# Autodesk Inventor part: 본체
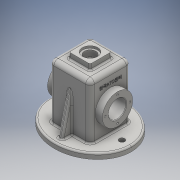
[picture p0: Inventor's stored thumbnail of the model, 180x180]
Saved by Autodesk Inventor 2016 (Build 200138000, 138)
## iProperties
Created: 2017-07
Part Number: 본체
Material: 일반
Document SubType Name: Modeling
Designer: USER
Density: 1 g/cm^3
Appearance: 기본값
Author: USER
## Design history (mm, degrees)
sketch "스케치1" dims "d14" = 75, "d15" = 65
  geometry: L1 (0, -65)-(0, 134.896); L2 (-82.834, 0)-(117.062, 0); L3 (-75, 53.384)-(-75, -73.215); L4 (75, 105.175)-(75, -110.044); 2 further points; 1 other entity
  constraints: 8 end point, 4 vertical, 4 vertical alignment, 2 horizontal alignment, 1 coincident, 1 horizontal, 1 perpendicular, 2 other
  dimensions: "d13" = 150 distance between parallel lines of L4 L3
extrude "돌출1" new body sketch "스케치1" distance "d16" = 10; taper "d17" = 0 deg
sketch "스케치2"
  geometry: L1 (-37, 110)-(37, 110); L2 (37, 110)-(37, 10); L3 (37, 10)-(-37, 10); L4 (-37, 10)-(-37, 110); L5 (65, 10)-(-65, 10) reference; L6 (-65, 0)-(65, 0) reference; 2 further points
  constraints: 8 end point, 2 parallel, 1 horizontal, 1 horizontal alignment, 1 midpoint, 1 perpendicular, 1 vertical alignment
  dimensions: "d18" = 74 distance between parallel lines of L2 L4; "d19" = 110 distance between parallel lines of L1 L6
extrude "돌출2" join sketch "스케치2" stored distance "d20" = 74; taper "d21" = 0 deg
sketch "스케치3"
  geometry: L1 (-37, 110)-(37, 110) reference; L2 (37, 110)-(37, 10) reference; L3 (-37, 10)-(37, 10) reference; L4 (-37, 10)-(-37, 110) reference; L5 (32, 105)-(-32, 105); L6 (-32, 105)-(-32, 15); L7 (-32, 15)-(32, 15); L8 (32, 15)-(32, 105); 1 further point
  constraints: 8 end point, 3 other
  dimensions: "d22" = 5 distance between parallel lines of L1 L5
extrude "돌출3" cut sketch "스케치3" stored distance "d23" = 64; taper "d24" = 0 deg
sketch "스케치4"
  geometry: L1 (-32, -32)-(32, -32); L2 (32, -32)-(32, 32); L3 (32, 32)-(-32, 32); L4 (-32, 32)-(-32, -32); 3 further points
  constraints: 8 end point, 2 midpoint, 2 parallel, 1 horizontal, 1 horizontal alignment, 1 perpendicular, 1 vertical alignment
  dimensions: "d25" = 64 distance of L3.end L1.start; "d26" = 64 distance of L2.end L3.end
extrude "돌출4" cut sketch "스케치4" stored distance "d27" = 69; taper "d28" = 0 deg
sketch "스케치5"
  geometry: 1 further point
sketch "스케치6"
  geometry: 1 further point
node "작업 평면1"
fillet "모깎기1" dims "d40" = 8
fillet "모깎기2" dims "d41" = 8
fillet "모깎기3" dims "d42" = 3
sketch "스케치15"
  geometry: L1 (0, 65)-(0, -65) reference; C1 r 27.5 at (55, 0); 2 further points
  constraints: 1 centre point, 1 horizontal alignment, 1 midpoint
  dimensions: "d56" = 55 diameter of C1; "d57" = 55 distance from line of L1 C1.centre
extrude "돌출7" join sketch "스케치15" distance "d58" = 13; taper "d59" = 0 deg
node "작업 평면2"
sketch "스케치16"
  geometry: C1 r 27.5 at (0, 0) reference; C2 r 16 at (0, 0); 1 further point
  constraints: 1 centre point, 1 coincident
  dimensions: "d60" = 32 diameter of C2
  node "투영된 루프3"
sketch "스케치17" dims "d63" = 45
  geometry: C1 r 27.5 at (0, 0) reference; 3 further points
  constraints: 2 horizontal alignment, 1 coincident, 2 other
hole "구멍2" sketch "스케치17" at (22.5, 0) diameter "d64" = 3.242; stored, may be unused: countersink angle "d68" = 90 deg, drill point angle "d70" = 118 deg; dims "d65" = 8, "d66" = 4, "d67" = 2, "d69" = 10
sketch "스케치18"
  geometry: L1 (65, 10)-(-65, 10) reference; L2 (-65, 0)-(65, 0) reference; L3 (65, 0)-(65, 10); L4 (55, 10)-(37, 82.194); L5 (37, 10)-(37, 102) reference; L6 (55, 10)-(37, 10); L7 (37, 82.194)-(37, 10); L8 (-37, 102)-(-37, 10) reference; L9 (-65, 10)-(-65, 0); L10 (-37, 82.194)-(-55, 10); L11 (-37, 82.194)-(-37, 10); L12 (65, 10)-(-65, 10) reference; L13 (-55, 10)-(-37, 10); 1 further point
  constraints: 16 end point, 4 point on line, 2 collinear, 2 perpendicular, 2 vertical
  dimensions: "d74" = 10 distance from line of L3 L4.start; "d75" = 14 deg angle of L4 L3; "d78" = 14 deg angle of L10 L9; "d79" = 10 distance from line of L9 L10.end
extrude "돌출9" join sketch "스케치18" stored distance "d80" = 8; taper "d81" = 0 deg
fillet "모깎기4" dims "d82" = 3
fillet "모깎기5" dims "d83" = 3
sketch "스케치19"
  geometry: L1 (86.305, 55)-(-68.103, 55); L2 (-29, 0)-(29, 0) reference; L3 (32, 102)-(32, 0) reference; L4 (32, 55)-(32, 82.5); L5 (32, 82.5)-(25, 75.5); L6 (25, 75.5)-(25, 55); 1 further point
  constraints: 8 end point, 4 point on line, 1 horizontal, 1 perpendicular
  dimensions: "d84" = 55 distance between parallel lines of L1 L2; "d85" = 7 distance between parallel lines of L3 L6; "d86" = 55 diameter of L4.end L1; "d87" = 135 deg angle of L3 L5
revolve "회전2" sketch "스케치19" stored, may be unused: angle "d88" = 90 deg
extrude "돌출10" cut sketch "스케치16" stored distance "d89" = 8; taper "d90" = 0 deg
sketch "스케치20"
  geometry: L1 (9, 9)-(49, 9); L2 (49, 9)-(49, 49); L3 (49, 49)-(9, 49); L4 (9, 49)-(9, 9); 3 further points
  constraints: 8 end point, 2 midpoint, 2 parallel, 1 horizontal, 1 horizontal alignment, 1 perpendicular, 1 vertical alignment
  dimensions: "d122" = 40 distance of L3.end L1.start; "d123" = 40 distance of L2.end L3.end
fillet "모깎기7" dims "d104" = 3
fillet "모깎기8" dims "d105" = 3
sketch "스케치23"
  geometry: L1 (-58, 0)-(58, 0); C1 r 5 at (-58, 0); C2 r 5 at (58, 0); 2 further points
  constraints: 2 centre point, 2 end point, 2 horizontal alignment, 1 coincident, 1 horizontal, 1 midpoint
  dimensions: "d106" = 10 diameter of C1; "d107" = 10 diameter of C2; "d109" = 58 distance of L1.start point (0, 0)
extrude "돌출14" cut sketch "스케치23" stored distance "d110" = 4; taper "d111" = 0 deg
chamfer "모따기1" distance "d112" = 1; stored, may be unused: second distance "d113" = 2, angle "d114" = 45 deg
extrude "돌출15" join sketch "스케치20" distance "d124" = 10; taper "d125" = -5 deg
sketch "스케치27"
  geometry: C1 r 14 at (29, 29); 1 further point
  constraints: 1 centre point, 1 coincident
  dimensions: "d126" = 28 diameter of C1
extrude "돌출16" cut sketch "스케치27" distance "d127" = 4; taper "d128" = 0 deg
sketch "스케치28"
  geometry: C1 r 10.5 at (0, 0); 1 further point
  constraints: 1 centre point, 1 coincident
  dimensions: "d129" = 21 diameter of C1
extrude "돌출17" cut sketch "스케치28" stored distance "d130" = 4; taper "d131" = 0 deg
fillet "모깎기10" dims "d132" = 3
fillet "모깎기11" dims "d133" = 3
sketch "스케치29"
  geometry: L1 (-120, 16.137)-(-120, -16.137) reference; L2 (-13, 37)-(-102, 37) reference; 2 further points
  constraints: 1 other
  dimensions: "d134" = 30 distance from line of point (-90, 0) L1; "d135" = 37 distance from line of L2 point (-90, 0)
feature "엠보싱2" sketch "스케치29" dims "d136" = 0.5, "d137" = 0
fillet "모깎기12" dims "d138" = 0.5
node "솔리드1"
mirror "대칭4"
mirror "대칭5"
mirror "대칭6"
pattern_circular "원형 패턴3" dims angle "d92" = 360 deg
mirror "대칭7"
node "투영된 루프1"
node "투영된 루프4"
